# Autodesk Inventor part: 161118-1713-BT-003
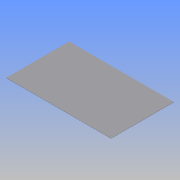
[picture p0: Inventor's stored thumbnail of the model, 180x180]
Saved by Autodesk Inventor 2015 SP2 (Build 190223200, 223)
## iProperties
Created: 2016-11
Part Number: 161118-1713-BT-003
Material: Generisch
Document SubType Name: Modeling
Designer: MP
Mass: 150000 g
Surface Area: 301600 cm^2
Volume: 150000 cm^3
Density: 1 g/cm^3
Appearance: Vorgabe
Author: MP
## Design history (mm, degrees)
sketch "Skizze1"
  geometry: L1 (0, 0)-(5000, 0); L2 (5000, 0)-(5000, 3000); L3 (5000, 3000)-(0, 3000); L4 (0, 3000)-(0, 0)
  constraints: 8 end point, 2 parallel, 1 horizontal, 1 perpendicular
  dimensions: "d0" = 5000 distance of L3.end L2.end; "d1" = 3000 distance of L2.end L1.end
extrude "Extrusion1" new body sketch "Skizze1" distance "d2" = 10; taper "d3" = 0 deg
sketch "Skizze2"
  geometry: 4 further points
workpoint "Arbeitspunkt1"
workpoint "Arbeitspunkt2"
workpoint "Arbeitspunkt3"
node "Volumenkörper1"
